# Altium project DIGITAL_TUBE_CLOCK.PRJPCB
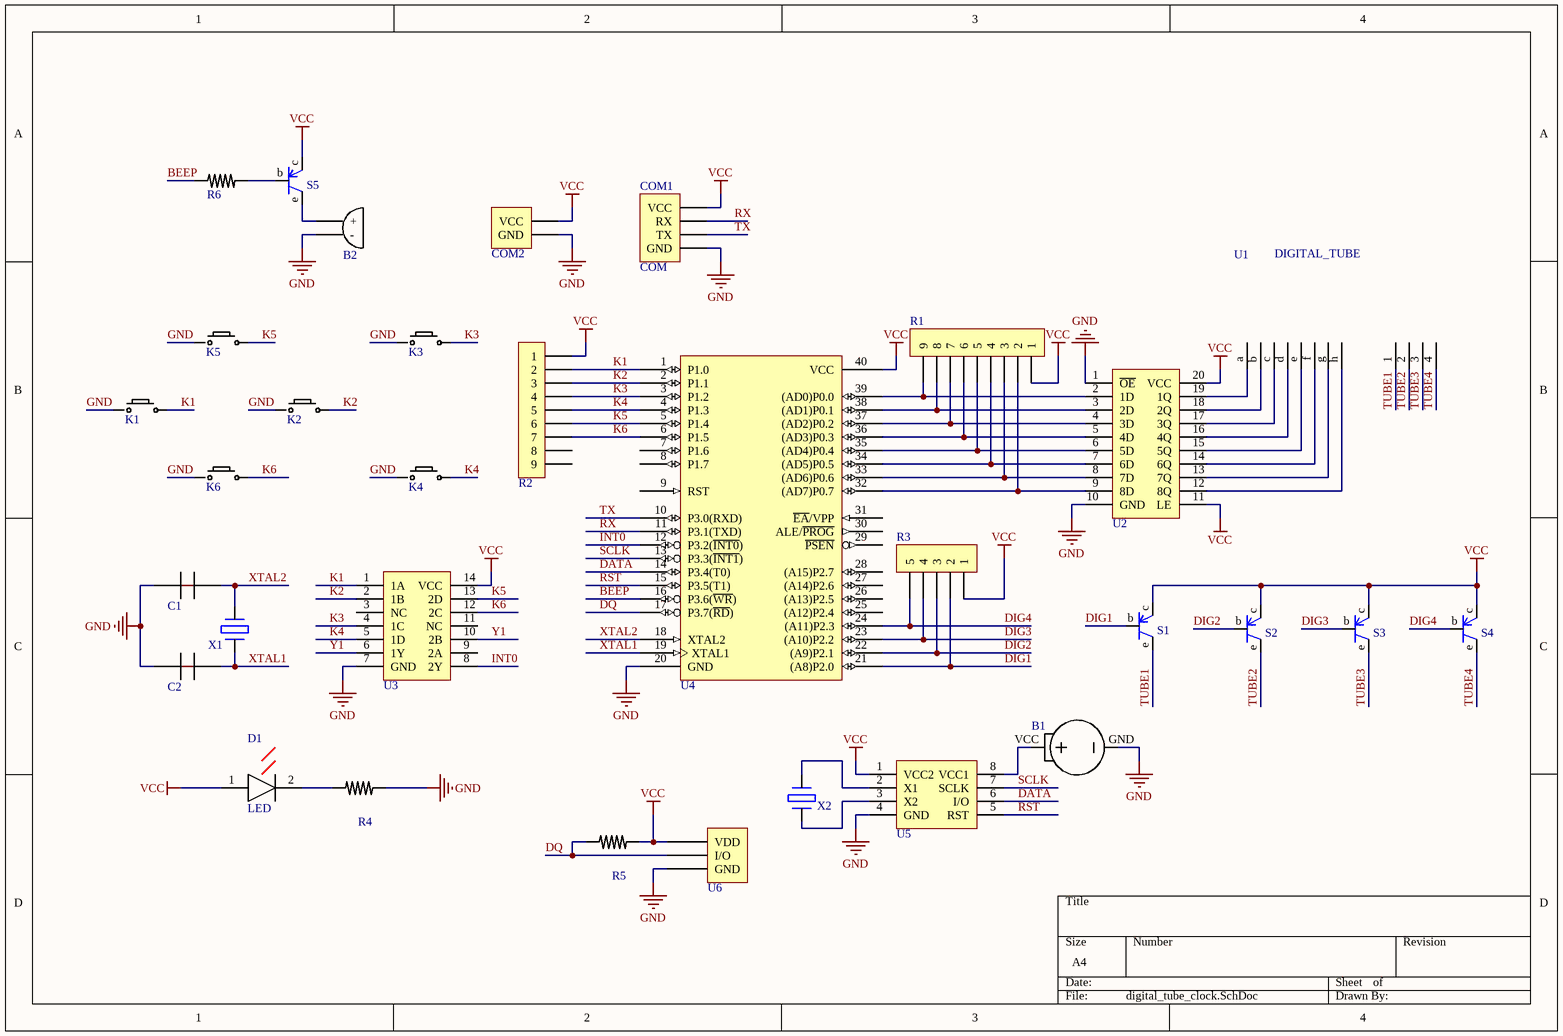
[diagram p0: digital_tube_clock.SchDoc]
1 sheet, 32 parts. Net scope: global (net labels, ports and power ports of the same name join across sheets).
Board file: digital_tube_clock.PcbDoc

## Sheet digital_tube_clock.SchDoc
size A4

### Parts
B1  BATTERY  [BAT]  (value not drawn)
B2  BEEP  [BEEP]  (value not drawn)
C1  CAP  [CAP]  (value not drawn)
C2  CAP  [CAP]  (value not drawn)
COM1  COM  [COM4]
COM2  COM  [COM2]  (value not drawn)
D1  LED  [LED]
K1  BUTTON  [BUTTON]  (value not drawn)
K2  BUTTON  [BUTTON]  (value not drawn)
K3  BUTTON  [BUTTON]  (value not drawn)
K4  BUTTON  [BUTTON]  (value not drawn)
K5  BUTTON  [BUTTON]  (value not drawn)
K6  BUTTON  [BUTTON]  (value not drawn)
R1  RES8  [RES8]  (value not drawn)
R2  RES8  [RES8]  (value not drawn)
R3  RES4  [RES4]  (value not drawn)
R4  RES  [RES]  (value not drawn)
R5  RES  [RES]  (value not drawn)
R6  RES  [RES]  (value not drawn)
S1  S9014  [S9014]  (value not drawn)
S2  S9014  [S9014]  (value not drawn)
S3  S9014  [S9014]  (value not drawn)
S4  S9014  [S9014]  (value not drawn)
S5  S9014  [S9014]  (value not drawn)
U1  DIGITAL_TUBE  [DIGITAL]
U2  SN74HC573AN  [SN74HC573AN]  (value not drawn)
U3  HD74LS21P  [HD74LS21P]  (value not drawn)
U4  STC89C52RC  [STC89C52RC]  (value not drawn)
U5  DS1302  [DS1302]  (value not drawn)
U6  DS18B20  [DS18B20]  (value not drawn)
X1  XTAL  [XTAL]  (value not drawn)
X2  36  [XTAL36]  (value not drawn)

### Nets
GND: B1.GND B2.2(-) C1.1 C2.1 COM1.GND COM2.GND K1.1 K2.1 K3.1 K4.1 K5.1 K6.1 R4.2 U2.1(~{OE}) U2.10(GND) U3.7(GND) U4.20(GND) U5.4(GND) U6.GND
VCC: COM1.VCC COM2.VCC D1.1 R1.1 R2.1 R3.1 R5.2 S1.c S2.c S3.c S4.c S5.c U2.11(LE) U2.20(VCC) U3.14(VCC) U4.40(VCC) U5.1(VCC2) U6.VDD
BEEP: R6.1 U4.16(P3.6(~{WR}))
DATA: U4.14(P3.4(T0)) U5.6(I/O)
DIG1: R3.2 S1.b U4.21((A8)P2.0)
DIG2: R3.3 S2.b U4.22((A9)P2.1)
DIG3: R3.4 S3.b U4.23((A10)P2.2)
DIG4: R3.5 S4.b U4.24((A11)P2.3)
DQ: R5.1 U4.17(P3.7(~{RD})) U6.DQ(I/O)
INT0: U3.8(2Y) U4.12(P3.2(~{INT0}))
K1: K1.2 R2.2 U3.1(1A) U4.1(P1.0)
K2: K2.2 R2.3 U3.2(1B) U4.2(P1.1)
K3: K3.2 R2.4 U3.4(1C) U4.3(P1.2)
K4: K4.2 R2.5 U3.5(1D) U4.4(P1.3)
K5: K5.2 R2.6 U3.13(2D) U4.5(P1.4)
K6: K6.2 R2.7 U3.12(2C) U4.6(P1.5)
RST: U4.15(P3.5(T1)) U5.5(RST)
RX: COM1.RX U4.11(P3.1(TXD))
SCLK: U4.13(P3.3(~{INT1})) U5.7(SCLK)
TUBE1: S1.e U1.1
TUBE2: S2.e U1.2
TUBE3: S3.e U1.3
TUBE4: S4.e U1.4
TX: COM1.TX U4.10(P3.0(RXD))
XTAL1: C2.2 U4.19(XTAL1) X1.1
XTAL2: C1.2 U4.18(XTAL2) X1.2
Y1: U3.6(1Y) U3.10(2B)
NetB1_VCC: B1.VCC U5.8(VCC1)
NetB2_1: B2.1(+) S5.e
NetD1_2: D1.2 R4.1
NetR1_2: R1.2 U2.9(8D) U4.32((AD7)P0.7)
NetR1_3: R1.3 U2.8(7D) U4.33((AD6)P0.6)
NetR1_4: R1.4 U2.7(6D) U4.34((AD5)P0.5)
NetR1_5: R1.5 U2.6(5D) U4.35((AD4)P0.4)
NetR1_6: R1.6 U2.5(4D) U4.36((AD3)P0.3)
NetR1_7: R1.7 U2.4(3D) U4.37((AD2)P0.2)
NetR1_8: R1.8 U2.3(2D) U4.38((AD1)P0.1)
NetR1_9: R1.9 U2.2(1D) U4.39((AD0)P0.0)
NetR6_2: R6.2 S5.b
NetU1_a: U1.a U2.19(1Q)
NetU1_b: U1.b U2.18(2Q)
NetU1_c: U1.c U2.17(3Q)
NetU1_d: U1.d U2.16(4Q)
NetU1_e: U1.e U2.15(5Q)
NetU1_f: U1.f U2.14(6Q)
NetU1_g: U1.g U2.13(7Q)
NetU1_h: U1.h U2.12(8Q)
NetU5_2: U5.2(X1) X2.2
NetU5_3: U5.3(X2) X2.1

Not connected (* = marked no-connect by the designer): R2 8 9; U3 3(NC) 9(2A) 11(NC); U4 7(P1.6) 8(P1.7) 9(RST) 25((A12)P2.4) 26((A13)P2.5) 27((A14)P2.6) 28((A15)P2.7) 29(~{PSEN}) 30(ALE/~{PROG}) 31(~{EA}/VPP)

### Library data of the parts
C1 C2 = CAP: Capacitance
COM1 = COM4: Download interface
COM2 = COM2: Power interface
D1 = LED: The power led
R1 R2 = RES8: Resistance * 8
R3 = RES4: Resistance * 4
R4-R6 = RES: Resistance
U1 = DIGITAL_TUBE: Dispaly panel
U4 = STC89C52RC: 8-Bit Microcontroller with 8K ISP Flash ROM
U5 = DS1302: Trickle Charge Timekeeping Chip
U6 = D18B20: Programmable Resolution  1-Wire Digital Thermometer
X1 = XTAL: Generate system clock
X2 = XTAL36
